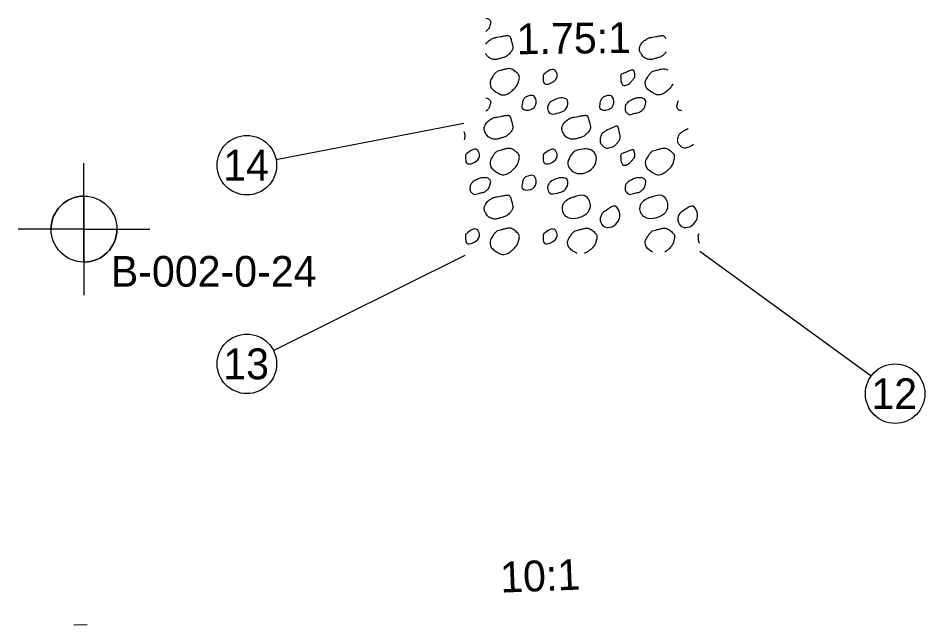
# Model space of a CAD drawing. Extents: x -1270 to 3371, y -118 to 220.
# Drawn here: x 128.18 to 169.48, y 113.47 to 141.08 of the extents above; entities that cross this region are included whole.
import ezdxf

# ---------------------------------------------------------------- set-up
doc = ezdxf.new("R2010")
doc.units = 0
for name, color, linetype in [('GE_P_Alignment', 7, 'Continuous'), ('GE_P_Alignment_100_Bearings', 7, 'Continuous'), ('PV_P_EOP', 7, 'Continuous'), ('TX_P_1', 7, 'Continuous'), ('XS_P_Finished_Grade', 7, 'Continuous')]:
    doc.layers.add(name, color=color, linetype=linetype)

msp = doc.modelspace()

# ---------------------------------------------------------------- linework, layer by layer
at = {"layer": 'GE_P_Alignment'}
for p, q in [((139.933, 134.647), (148.483, 136.296)), ((139.816, 125.953), (148.544, 130.297)), ((167.033, 124.789), (159.232, 130.464))]:
    msp.add_line(p, q, dxfattribs=at)
at = {"layer": 'GE_P_Alignment_100_Bearings'}
for points, degree in [([(149.483, 141.081), (149.542, 141.076), (149.598, 141.055), (149.651, 141.002), (149.712, 140.942), (149.703, 140.862), (149.685, 140.798), (149.656, 140.694), (149.617, 140.587), (149.514, 140.502), (149.504, 140.493), (149.494, 140.485), (149.483, 140.478)], 3), ([(149.976, 140.211), (150.127, 140.237), (150.279, 140.266), (150.43, 140.287), (150.581, 140.308), (150.652, 140.049), (150.689, 139.907), (150.724, 139.778), (150.702, 139.621), (150.593, 139.5), (150.46, 139.353), (150.311, 139.296), (150.147, 139.248), (150.006, 139.206), (149.848, 139.191), (149.707, 139.25), (149.622, 139.286), (149.56, 139.348), (149.508, 139.428), (149.499, 139.442), (149.491, 139.456), (149.483, 139.471)], 3), ([(149.483, 139.893), (149.532, 139.969), (149.596, 140.036), (149.676, 140.087), (149.75, 140.134), (149.82, 140.178), (149.902, 140.195), (149.929, 140.201), (149.957, 140.207), (149.984, 140.213)], 3), ([(157.706, 139.555), (157.694, 139.536), (157.68, 139.518), (157.664, 139.5), (157.531, 139.353), (157.383, 139.296), (157.219, 139.248), (157.077, 139.206), (156.919, 139.191), (156.779, 139.25), (156.693, 139.286), (156.631, 139.348), (156.579, 139.428), (156.493, 139.562), (156.467, 139.747), (156.543, 139.873), (156.593, 139.957), (156.661, 140.031), (156.748, 140.087), (156.821, 140.134), (156.892, 140.178), (156.974, 140.195), (157.001, 140.201), (157.029, 140.207), (157.056, 140.213)], 3), ([(157.048, 140.211), (157.199, 140.237), (157.351, 140.266), (157.502, 140.287), (157.577, 140.297), (157.633, 140.238), (157.674, 140.158)], 3), ([(149.997, 138.659), (150.115, 138.691), (150.234, 138.722), (150.353, 138.753), (150.526, 138.798), (150.7, 138.766), (150.874, 138.621), (151.008, 138.509), (151.017, 138.343), (150.981, 138.218), (150.936, 138.062), (150.837, 137.913), (150.685, 137.783), (150.495, 137.621), (150.231, 137.558), (150.037, 137.673), (149.879, 137.766), (149.713, 137.906), (149.683, 138.071), (149.664, 138.174), (149.717, 138.294), (149.778, 138.389), (149.821, 138.458), (149.859, 138.527), (149.916, 138.582), (149.943, 138.608), (149.97, 138.634), (149.997, 138.659)], 3), ([(157.069, 138.659), (157.187, 138.691), (157.306, 138.722), (157.424, 138.753), (157.543, 138.783), (157.661, 138.778), (157.78, 138.726)], 3), ([(155.669, 138.533), (155.828, 138.598), (155.986, 138.666), (156.144, 138.726), (156.222, 138.756), (156.263, 138.582), (156.27, 138.508), (156.28, 138.408), (156.203, 138.304), (156.121, 138.205), (156.01, 138.071), (155.729, 137.973), (155.671, 138.121), (155.64, 138.199), (155.635, 138.28), (155.632, 138.361), (155.63, 138.401), (155.615, 138.446), (155.636, 138.482), (155.647, 138.5), (155.659, 138.516), (155.669, 138.533)], 3), ([(158, 138.084), (157.946, 137.977), (157.865, 137.875), (157.757, 137.783), (157.567, 137.621), (157.303, 137.558), (157.109, 137.673), (156.951, 137.766), (156.785, 137.906), (156.754, 138.071), (156.735, 138.174), (156.789, 138.294), (156.849, 138.389), (156.893, 138.458), (156.931, 138.527), (156.988, 138.582), (157.015, 138.608), (157.042, 138.634), (157.069, 138.659)], 3), ([(149.483, 137.451), (149.542, 137.446), (149.598, 137.424), (149.651, 137.371), (149.712, 137.311), (149.703, 137.231), (149.685, 137.168), (149.656, 137.063), (149.617, 136.956), (149.514, 136.871), (149.504, 136.863), (149.494, 136.855), (149.483, 136.848)], 3), ([(155.961, 137.27), (156.044, 137.312), (156.128, 137.353), (156.211, 137.395), (156.303, 137.44), (156.412, 137.449), (156.512, 137.452), (156.585, 137.454), (156.656, 137.437), (156.723, 137.371), (156.783, 137.311), (156.775, 137.231), (156.757, 137.168), (156.727, 137.063), (156.688, 136.956), (156.586, 136.871), (156.486, 136.788), (156.38, 136.776), (156.273, 136.751), (156.16, 136.725), (156.031, 136.658), (155.921, 136.757), (155.848, 136.822), (155.833, 136.899), (155.835, 136.973), (155.837, 137.039), (155.845, 137.118), (155.887, 137.173), (155.912, 137.206), (155.936, 137.238), (155.961, 137.27)], 3), ([(158.415, 136.87), (158.332, 136.875), (158.252, 136.909), (158.219, 136.976), (158.18, 137.054), (158.199, 137.144), (158.221, 137.222), (158.232, 137.261), (158.239, 137.303), (158.254, 137.341)], 3), ([(149.976, 136.581), (150.127, 136.606), (150.279, 136.635), (150.43, 136.656), (150.581, 136.677), (150.652, 136.418), (150.689, 136.276), (150.724, 136.147), (150.702, 135.99), (150.593, 135.87), (150.46, 135.722), (150.311, 135.666), (150.147, 135.617), (150.006, 135.576), (149.848, 135.56), (149.707, 135.62), (149.622, 135.656), (149.56, 135.718), (149.508, 135.798), (149.421, 135.932), (149.396, 136.117), (149.471, 136.243), (149.521, 136.327), (149.589, 136.401), (149.676, 136.456), (149.75, 136.503), (149.82, 136.547), (149.902, 136.565), (149.929, 136.571), (149.957, 136.576), (149.984, 136.582)], 3), ([(153.512, 136.581), (153.663, 136.606), (153.815, 136.635), (153.966, 136.656), (154.117, 136.677), (154.187, 136.418), (154.225, 136.276), (154.26, 136.147), (154.237, 135.99), (154.129, 135.87), (153.995, 135.722), (153.847, 135.666), (153.683, 135.617), (153.542, 135.576), (153.383, 135.56), (153.243, 135.62), (153.157, 135.656), (153.095, 135.718), (153.044, 135.798), (152.957, 135.932), (152.931, 136.117), (153.007, 136.243), (153.057, 136.327), (153.125, 136.401), (153.212, 136.456), (153.286, 136.503), (153.356, 136.547), (153.438, 136.565), (153.465, 136.571), (153.493, 136.576), (153.52, 136.582)], 3), ([(148.487, 135.929), (148.499, 135.885), (148.508, 135.843), (148.515, 135.811), (148.533, 135.727), (148.526, 135.637), (148.491, 135.549)], 3), ([(155.028, 135.998), (155.145, 136.048), (155.262, 136.099), (155.379, 136.149), (155.501, 136.201), (155.56, 135.934), (155.587, 135.811), (155.615, 135.679), (155.581, 135.533), (155.475, 135.406), (155.376, 135.286), (155.262, 135.229), (155.142, 135.193), (155.046, 135.164), (154.925, 135.159), (154.831, 135.252), (154.717, 135.365), (154.675, 135.497), (154.698, 135.611), (154.716, 135.702), (154.758, 135.822), (154.844, 135.879), (154.905, 135.92), (154.967, 135.958), (155.028, 135.998)], 3), ([(158.941, 135.333), (158.859, 135.261), (158.77, 135.221), (158.678, 135.193), (158.582, 135.164), (158.461, 135.159), (158.367, 135.252), (158.253, 135.365), (158.211, 135.497), (158.234, 135.611), (158.252, 135.702), (158.294, 135.822), (158.379, 135.879), (158.441, 135.92), (158.502, 135.958), (158.564, 135.998)], 3), ([(158.564, 135.998), (158.607, 136.017), (158.651, 136.035), (158.694, 136.054)], 2), ([(149.997, 135.029), (150.115, 135.06), (150.234, 135.091), (150.353, 135.122), (150.526, 135.167), (150.7, 135.135), (150.874, 134.991), (151.008, 134.878), (151.017, 134.712), (150.981, 134.588), (150.936, 134.431), (150.837, 134.283), (150.685, 134.153), (150.495, 133.991), (150.231, 133.927), (150.037, 134.042), (149.879, 134.135), (149.713, 134.275), (149.683, 134.441), (149.664, 134.543), (149.717, 134.663), (149.778, 134.759), (149.821, 134.827), (149.859, 134.896), (149.916, 134.951), (149.943, 134.977), (149.97, 135.003), (149.997, 135.029)], 3), ([(155.669, 134.903), (155.828, 134.967), (155.986, 135.035), (156.144, 135.096), (156.222, 135.125), (156.263, 134.952), (156.27, 134.877), (156.28, 134.778), (156.203, 134.673), (156.121, 134.575), (156.01, 134.441), (155.729, 134.343), (155.671, 134.491), (155.64, 134.569), (155.635, 134.65), (155.632, 134.731), (155.63, 134.771), (155.615, 134.815), (155.636, 134.851), (155.647, 134.87), (155.659, 134.886), (155.669, 134.903)], 3), ([(157.069, 135.029), (157.187, 135.06), (157.306, 135.091), (157.424, 135.122), (157.598, 135.167), (157.772, 135.135), (157.945, 134.991), (158.08, 134.878), (158.088, 134.712), (158.053, 134.588), (158.008, 134.431), (157.909, 134.283), (157.757, 134.153), (157.567, 133.991), (157.303, 133.927), (157.109, 134.042), (156.951, 134.135), (156.785, 134.275), (156.754, 134.441), (156.735, 134.543), (156.789, 134.663), (156.849, 134.759), (156.893, 134.827), (156.931, 134.896), (156.988, 134.951), (157.015, 134.977), (157.042, 135.003), (157.069, 135.029)], 3), ([(148.889, 133.639), (148.973, 133.681), (149.056, 133.723), (149.139, 133.764), (149.231, 133.81), (149.341, 133.819), (149.44, 133.822), (149.514, 133.824), (149.585, 133.807), (149.651, 133.741), (149.712, 133.681), (149.703, 133.601), (149.685, 133.538), (149.656, 133.433), (149.617, 133.326), (149.514, 133.241), (149.414, 133.158), (149.309, 133.146), (149.201, 133.121), (149.088, 133.095), (148.96, 133.028), (148.849, 133.127), (148.777, 133.192), (148.762, 133.268), (148.764, 133.343), (148.765, 133.409), (148.774, 133.487), (148.815, 133.543), (148.84, 133.575), (148.865, 133.607), (148.889, 133.639)], 3), ([(155.961, 133.639), (156.044, 133.681), (156.128, 133.723), (156.211, 133.764), (156.303, 133.81), (156.412, 133.819), (156.512, 133.822), (156.585, 133.824), (156.656, 133.807), (156.723, 133.741), (156.783, 133.681), (156.775, 133.601), (156.757, 133.538), (156.727, 133.433), (156.688, 133.326), (156.586, 133.241), (156.486, 133.158), (156.38, 133.146), (156.273, 133.121), (156.16, 133.095), (156.031, 133.028), (155.921, 133.127), (155.848, 133.192), (155.833, 133.268), (155.835, 133.343), (155.837, 133.409), (155.845, 133.487), (155.887, 133.543), (155.912, 133.575), (155.936, 133.607), (155.961, 133.639)], 3), ([(149.976, 132.95), (150.127, 132.976), (150.279, 133.005), (150.43, 133.026), (150.581, 133.047), (150.652, 132.788), (150.689, 132.646), (150.724, 132.517), (150.702, 132.36), (150.593, 132.239), (150.46, 132.092), (150.311, 132.035), (150.147, 131.987), (150.006, 131.945), (149.848, 131.93), (149.707, 131.989), (149.622, 132.025), (149.56, 132.087), (149.508, 132.168), (149.421, 132.301), (149.396, 132.486), (149.471, 132.613), (149.521, 132.696), (149.589, 132.77), (149.676, 132.826), (149.75, 132.873), (149.82, 132.917), (149.902, 132.934), (149.929, 132.94), (149.957, 132.946), (149.984, 132.952)], 3), ([(149.997, 131.398), (150.115, 131.43), (150.234, 131.461), (150.353, 131.492), (150.526, 131.537), (150.7, 131.505), (150.874, 131.36), (151.008, 131.248), (151.017, 131.082), (150.981, 130.958), (150.936, 130.801), (150.837, 130.652), (150.685, 130.523), (150.495, 130.36), (150.231, 130.297), (150.037, 130.412), (149.879, 130.505), (149.713, 130.645), (149.683, 130.81), (149.664, 130.913), (149.717, 131.033), (149.778, 131.128), (149.821, 131.197), (149.859, 131.266), (149.916, 131.321), (149.943, 131.347), (149.97, 131.373), (149.997, 131.398)], 3), ([(153.649, 130.377), (153.623, 130.386), (153.597, 130.397), (153.573, 130.412), (153.415, 130.505), (153.249, 130.645), (153.219, 130.81), (153.2, 130.913), (153.253, 131.033), (153.314, 131.128), (153.357, 131.197), (153.395, 131.266), (153.452, 131.321), (153.479, 131.347), (153.506, 131.373), (153.533, 131.398)], 3), ([(153.533, 131.398), (153.651, 131.43), (153.77, 131.461), (153.889, 131.492), (154.062, 131.537), (154.236, 131.505), (154.409, 131.36), (154.544, 131.248), (154.553, 131.082), (154.517, 130.958), (154.472, 130.801), (154.373, 130.652), (154.221, 130.523), (154.146, 130.459), (154.06, 130.41), (153.971, 130.382)], 3), ([(157.078, 130.43), (156.93, 130.523), (156.783, 130.656), (156.754, 130.81), (156.735, 130.913), (156.789, 131.033), (156.849, 131.128), (156.893, 131.197), (156.931, 131.266), (156.988, 131.321), (157.015, 131.347), (157.042, 131.373), (157.069, 131.398)], 3), ([(157.069, 131.398), (157.187, 131.43), (157.306, 131.461), (157.424, 131.492), (157.598, 131.537), (157.772, 131.505), (157.945, 131.36), (158.08, 131.248), (158.088, 131.082), (158.053, 130.958), (158.008, 130.801), (157.909, 130.652), (157.757, 130.523), (157.72, 130.491), (157.68, 130.463), (157.638, 130.439)], 3), ([(159.215, 130.843), (159.212, 130.848), (159.209, 130.854), (159.207, 130.86), (159.176, 130.938), (159.171, 131.019), (159.168, 131.1), (159.166, 131.14), (159.151, 131.185), (159.172, 131.221), (159.18, 131.235), (159.189, 131.247), (159.197, 131.26)], 3)]:
    msp.add_open_spline(points, degree=degree, dxfattribs=at)
for points in [[(152.134, 138.533), (152.609, 138.726), (152.734, 138.508), (152.585, 138.205), (152.135, 138.121), (152.096, 138.361), (152.1, 138.482), (152.134, 138.533)], [(151.288, 137.486), (151.669, 137.542), (151.774, 137.214), (151.534, 136.92), (151.147, 136.976), (151.149, 137.222), (151.208, 137.386), (151.288, 137.486)], [(154.824, 137.486), (155.205, 137.542), (155.309, 137.214), (155.069, 136.92), (154.683, 136.976), (154.685, 137.222), (154.744, 137.386), (154.824, 137.486)], [(152.425, 137.27), (152.675, 137.395), (152.976, 137.452), (153.187, 137.371), (153.221, 137.168), (153.05, 136.871), (152.737, 136.751), (152.385, 136.757), (152.299, 136.973), (152.351, 137.173), (152.425, 137.27)], [(148.598, 134.903), (149.073, 135.096), (149.199, 134.877), (149.049, 134.575), (148.599, 134.491), (148.56, 134.731), (148.564, 134.851), (148.598, 134.903)], [(152.134, 134.903), (152.609, 135.096), (152.734, 134.877), (152.585, 134.575), (152.135, 134.491), (152.096, 134.731), (152.1, 134.851), (152.134, 134.903)], [(153.533, 135.029), (153.889, 135.122), (154.409, 134.991), (154.517, 134.588), (154.221, 134.153), (153.573, 134.042), (153.219, 134.441), (153.314, 134.759), (153.452, 134.951), (153.533, 135.029)], [(151.288, 133.856), (151.669, 133.912), (151.774, 133.583), (151.534, 133.289), (151.147, 133.346), (151.149, 133.592), (151.208, 133.755), (151.288, 133.856)], [(152.425, 133.639), (152.675, 133.764), (152.976, 133.822), (153.187, 133.741), (153.221, 133.538), (153.05, 133.241), (152.737, 133.121), (152.385, 133.127), (152.299, 133.343), (152.351, 133.543), (152.425, 133.639)], [(153.512, 132.95), (153.966, 133.026), (154.225, 132.646), (154.129, 132.239), (153.683, 131.987), (153.243, 131.989), (153.044, 132.168), (153.007, 132.613), (153.212, 132.826), (153.438, 132.934), (153.52, 132.952)], [(157.048, 132.95), (157.502, 133.026), (157.761, 132.646), (157.664, 132.239), (157.219, 131.987), (156.779, 131.989), (156.579, 132.168), (156.543, 132.613), (156.748, 132.826), (156.974, 132.934), (157.056, 132.952)], [(155.028, 132.368), (155.379, 132.518), (155.587, 132.18), (155.475, 131.775), (155.142, 131.563), (154.831, 131.622), (154.698, 131.981), (154.844, 132.248), (155.028, 132.368)], [(158.564, 132.368), (158.915, 132.518), (159.123, 132.18), (159.011, 131.775), (158.678, 131.563), (158.367, 131.622), (158.234, 131.981), (158.379, 132.248), (158.564, 132.368)], [(148.598, 131.273), (149.073, 131.465), (149.199, 131.247), (149.049, 130.944), (148.599, 130.86), (148.56, 131.1), (148.564, 131.221), (148.598, 131.273)], [(152.134, 131.273), (152.609, 131.465), (152.734, 131.247), (152.585, 130.944), (152.135, 130.86), (152.096, 131.1), (152.1, 131.221), (152.134, 131.273)]]:
    msp.add_spline(points, degree=3, dxfattribs=at)
at = {"layer": 'PV_P_EOP'}
msp.add_line((130.719, 113.473), (131.319, 113.496), dxfattribs=at)
at = {"layer": 'TX_P_1'}
for centre in [(138.603, 134.39), (138.603, 125.35), (168.128, 123.992)]:
    msp.add_circle(centre, 1.355, dxfattribs=at)
at = {"layer": 'XS_P_Finished_Grade'}
for p, q in [((131.182, 131.483), (131.182, 134.483)), ((131.182, 132.983), (131.182, 131.483)), ((131.182, 131.483), (128.182, 131.483)), ((131.182, 131.483), (129.682, 131.483)), ((131.182, 131.483), (131.182, 128.483)), ((131.182, 131.483), (134.182, 131.483)), ((131.182, 129.983), (131.182, 131.483)), ((131.182, 131.483), (132.682, 131.483))]:
    msp.add_line(p, q, dxfattribs=at)
msp.add_circle((131.182, 131.483), 1.5, dxfattribs=at)
for start, end in [(90, 180), (270, 360)]:
    msp.add_arc((131.182, 131.483), 1.5, start, end, dxfattribs=at)

# ---------------------------------------------------------------- texts
at = {"layer": 'GE_P_Alignment'}
for s, rotation, p in [('1.75:1', 0.7499, (150.898, 139.436)), ('10:1', 2.2498, (150.166, 114.937))]:
    msp.add_text(s, height=1.4, rotation=rotation, dxfattribs=at).set_placement(p)
at = {"layer": 'TX_P_1'}
for s, p in [('14', (137.526, 133.69)), ('B-002-0-24', (132.406, 128.86)), ('13', (137.526, 124.65)), ('12', (167.047, 123.292))]:
    msp.add_text(s, height=1.4, dxfattribs=at).set_placement(p)

doc.saveas('drawing.dxf')
